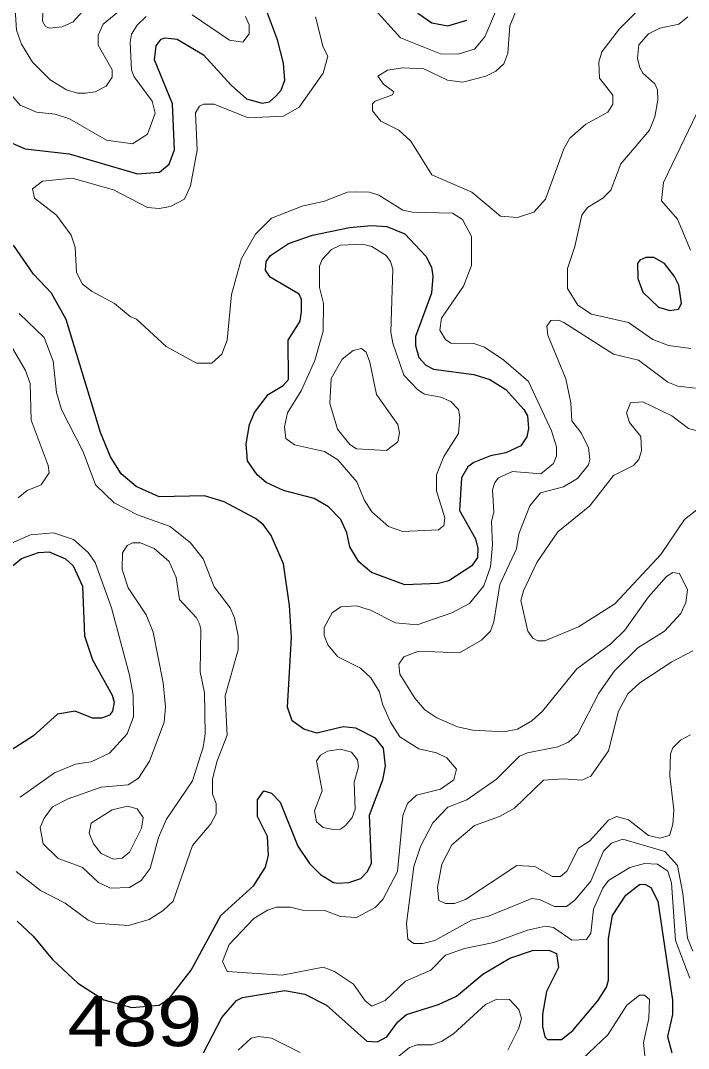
# Model space of a CAD drawing. Extents: x 577 to 602.9, y 7483.8 to 7511.6.
# Drawn here: x 583.474 to 584.536, y 7499.086 to 7500.722 of the extents above; entities that cross this region are included whole.
import ezdxf
from ezdxf.enums import TextEntityAlignment as Align

# ---------------------------------------------------------------- set-up
doc = ezdxf.new("R2010")
doc.units = 0
doc.header["$LTSCALE"] = 0.032
doc.layers.add('1', color=7, linetype='Continuous', lineweight=25)
doc.layers.add('2', color=7, linetype='Continuous', lineweight=13)
doc.layers.add('61', color=7, linetype='Continuous')

msp = doc.modelspace()

# ---------------------------------------------------------------- linework, layer by layer
at = {"layer": '1'}
for points in [[(583.3895, 7500.558), (583.4809, 7500.5182), (583.5509, 7500.5103), (583.6599, 7500.4785), (583.6948, 7500.4809), (583.71, 7500.4936), (583.7187, 7500.5166), (583.7155, 7500.5898), (583.6869, 7500.6598), (583.6893, 7500.682), (583.6972, 7500.6924), (583.7036, 7500.6948), (583.7227, 7500.6924), (583.7648, 7500.6677), (583.8086, 7500.6192), (583.8332, 7500.5977), (583.8579, 7500.5906), (583.8698, 7500.593), (583.8801, 7500.6017), (583.8881, 7500.6113), (583.8944, 7500.6272), (583.892, 7500.6542), (583.8825, 7500.6916), (583.8666, 7500.7337)], [(584.1059, 7500.7337), (584.1282, 7500.7186), (584.1537, 7500.7138), (584.1839, 7500.7226)], [(584.0384, 7499.5799), (584.0073, 7499.5958), (583.9867, 7499.5982), (583.9453, 7499.5879), (583.9246, 7499.5942), (583.9056, 7499.6078), (583.8984, 7499.6292), (583.9048, 7499.7405), (583.9016, 7499.7914), (583.892, 7499.8574), (583.8722, 7499.9028), (583.8602, 7499.9195), (583.8475, 7499.9298), (583.7974, 7499.956), (583.7664, 7499.9656), (583.694, 7499.964), (583.6575, 7499.9807), (583.6336, 7500.0006), (583.6169, 7500.0276), (583.601, 7500.0666), (583.5461, 7500.2463), (583.5231, 7500.2884), (583.4945, 7500.3186), (583.4627, 7500.3648)], [(583.4571, 7499.8511), (583.4754, 7499.8662), (583.5024, 7499.8757), (583.5191, 7499.8765), (583.5454, 7499.8654), (583.5573, 7499.8543), (583.5724, 7499.8217), (583.5756, 7499.7429), (583.5883, 7499.7048), (583.6193, 7499.6483), (583.6225, 7499.6372), (583.6201, 7499.6229), (583.6153, 7499.6165), (583.6026, 7499.6117), (583.5883, 7499.6117), (583.5605, 7499.6229), (583.5326, 7499.6181), (583.4945, 7499.5839), (583.4269, 7499.541)], [(583.4682, 7499.2889), (583.4937, 7499.265), (583.5247, 7499.2277), (583.5649, 7499.1902), (583.606, 7499.1637), (583.6506, 7499.1514), (583.694, 7499.1553), (583.71, 7499.1656), (583.7449, 7499.211), (583.7926, 7499.2976), (583.8451, 7499.3453), (583.8634, 7499.3748), (583.8682, 7499.3931), (583.8666, 7499.4233), (583.8507, 7499.4551), (583.8507, 7499.4821), (583.861, 7499.4964), (583.873, 7499.4925), (583.8865, 7499.4781), (583.9151, 7499.4082), (583.9334, 7499.3803), (583.9509, 7499.3628), (583.9716, 7499.3501), (583.9787, 7499.3493), (583.9962, 7499.3501), (584.0153, 7499.3565), (584.0256, 7499.3676), (584.032, 7499.3811), (584.0288, 7499.4575), (584.0503, 7499.5139), (584.0543, 7499.5354), (584.0511, 7499.564), (584.0384, 7499.5799)], [(583.7648, 7499.079), (583.7942, 7499.1354), (583.8173, 7499.1625), (583.8268, 7499.1672), (583.8944, 7499.1784), (583.9262, 7499.1728), (583.9604, 7499.1553), (584.0248, 7499.098), (584.0415, 7499.0965), (584.0566, 7499.1044), (584.0741, 7499.1283), (584.0877, 7499.1402), (584.1386, 7499.1561), (584.1672, 7499.1696), (584.2093, 7499.2046), (584.2523, 7499.23), (584.288, 7499.242), (584.3143, 7499.2428), (584.3262, 7499.2372), (584.3294, 7499.2149), (584.3103, 7499.1768), (584.3039, 7499.141), (584.3039, 7499.1211), (584.3079, 7499.1044), (584.3119, 7499.1004), (584.3342, 7499.1004), (584.3525, 7499.1147), (584.3922, 7499.1617), (584.4057, 7499.1839), (584.4089, 7499.1951), (584.4089, 7499.2611), (584.4153, 7499.2976), (584.4367, 7499.3302), (584.4582, 7499.3469), (584.467, 7499.3477), (584.4765, 7499.3422), (584.4876, 7499.3207), (584.5107, 7499.1632), (584.5107, 7499.1402), (584.5027, 7499.1052), (584.5099, 7499.079)]]:
    msp.add_lwpolyline(points, dxfattribs=at)
for points in [[(584.2205, 7500.1509), (584.2459, 7500.135), (584.2745, 7500.1031), (584.2801, 7500.0928), (584.2817, 7500.0729), (584.2793, 7500.0594), (584.2698, 7500.0451), (584.2459, 7500.034), (584.2212, 7500.0292), (584.195, 7500.0189), (584.1855, 7500.0117), (584.1751, 7499.9942), (584.1719, 7499.9425), (584.1974, 7499.8972), (584.2014, 7499.8821), (584.2006, 7499.8678), (584.1918, 7499.8543), (584.1552, 7499.8304), (584.1386, 7499.8264), (584.0853, 7499.824), (584.032, 7499.8439), (584.0121, 7499.8606), (583.9978, 7499.8845), (583.993, 7499.9067), (583.9835, 7499.9282), (583.9636, 7499.9481), (583.9406, 7499.9616), (583.892, 7499.9743), (583.8642, 7499.9871), (583.8499, 7499.999), (583.8348, 7500.0212), (583.8324, 7500.0483), (583.838, 7500.0793), (583.8459, 7500.0984), (583.8674, 7500.127), (583.8913, 7500.1413), (583.9, 7500.1509), (583.8992, 7500.2137), (583.9183, 7500.2439), (583.9207, 7500.259), (583.9207, 7500.2781), (583.9167, 7500.2868), (583.8706, 7500.3139), (583.8634, 7500.325), (583.8642, 7500.3385), (583.8714, 7500.3481), (583.9, 7500.3671), (583.9382, 7500.3807), (583.997, 7500.3926), (584.032, 7500.3958), (584.0566, 7500.3942), (584.0853, 7500.383), (584.1187, 7500.3473), (584.1274, 7500.3298), (584.1298, 7500.3155), (584.1274, 7500.2884), (584.102, 7500.2192), (584.102, 7500.2049), (584.1075, 7500.1858), (584.1187, 7500.1739), (584.1306, 7500.1676), (584.195, 7500.1588)], [(584.5141, 7500.315), (584.498, 7500.3353), (584.4813, 7500.3449), (584.4685, 7500.3449), (584.459, 7500.3409), (584.455, 7500.3353), (584.4558, 7500.3115), (584.4638, 7500.29), (584.4884, 7500.2662), (584.5067, 7500.2606), (584.5202, 7500.263), (584.525, 7500.2717), (584.521, 7500.3011)]]:
    msp.add_lwpolyline(points, close=True, dxfattribs=at)
at = {"layer": '2'}
for points in [[(583.6455, 7500.8252), (583.6543, 7500.8124), (583.6543, 7500.8021), (583.6471, 7500.7918), (583.605, 7500.7735), (583.5573, 7500.7202), (583.5398, 7500.7123), (583.5199, 7500.7099), (583.5135, 7500.713), (583.5088, 7500.721), (583.5096, 7500.7441), (583.5398, 7500.7751), (583.5644, 7500.8069), (583.578, 7500.8164), (583.6113, 7500.8276), (583.6304, 7500.8299)], [(584.1059, 7500.1342), (584.1163, 7500.1278), (584.1425, 7500.123), (584.1584, 7500.1159), (584.1704, 7500.1031), (584.1727, 7500.0912), (584.1704, 7500.065), (584.1473, 7500.0284), (584.1354, 7499.999), (584.1354, 7499.9735), (584.1489, 7499.9306), (584.1473, 7499.9187), (584.1386, 7499.9115), (584.0821, 7499.9091), (584.059, 7499.9171), (584.0328, 7499.9401), (584.0201, 7499.9592), (584.0089, 7499.9878), (583.9787, 7500.0228), (583.9573, 7500.0364), (583.9095, 7500.0467), (583.896, 7500.057), (583.8936, 7500.0753), (583.8984, 7500.0976), (583.9199, 7500.1326), (583.9421, 7500.1811), (583.9549, 7500.228), (583.9557, 7500.2717), (583.9493, 7500.2972), (583.9493, 7500.3314), (583.9533, 7500.3417), (583.9684, 7500.3576), (583.9827, 7500.3648), (584.0177, 7500.3663), (584.0328, 7500.3624), (584.0551, 7500.3481), (584.0622, 7500.3385), (584.0662, 7500.3266), (584.063, 7500.2264), (584.0662, 7500.2089), (584.0837, 7500.158)], [(584.0606, 7500.0976), (584.0741, 7500.0793), (584.0765, 7500.0658), (584.0741, 7500.0515), (584.0559, 7500.0379), (584.0081, 7500.0403), (583.9978, 7500.0475), (583.9779, 7500.0721), (583.966, 7500.1127), (583.9676, 7500.1524), (583.9851, 7500.1835), (584.0026, 7500.197), (584.0161, 7500.2002), (584.0233, 7500.1946), (584.0296, 7500.1787), (584.0399, 7500.127)], [(583.5628, 7499.3779), (583.5724, 7499.374), (583.5978, 7499.3501), (583.6169, 7499.3414), (583.6471, 7499.3422), (583.6654, 7499.3533), (583.6797, 7499.3724), (583.6933, 7499.4217), (583.706, 7499.4511), (583.7473, 7499.5123), (583.764, 7499.5656), (583.7672, 7499.5871), (583.7664, 7499.6523), (583.7593, 7499.6857), (583.7608, 7499.7533), (583.7585, 7499.762), (583.7537, 7499.7716), (583.7267, 7499.801), (583.7211, 7499.836), (583.71, 7499.8614), (583.6861, 7499.8821), (583.6646, 7499.8908), (583.6519, 7499.8908), (583.6432, 7499.8869), (583.636, 7499.8749), (583.6352, 7499.8487), (583.6447, 7499.8193), (583.6734, 7499.7763), (583.6845, 7499.7485), (583.7004, 7499.6682), (583.7044, 7499.63), (583.702, 7499.6054), (583.6789, 7499.5433), (583.6614, 7499.5163), (583.6447, 7499.506), (583.6018, 7499.502), (583.5493, 7499.4837), (583.5247, 7499.471), (583.5112, 7499.4527), (583.5048, 7499.4376), (583.5096, 7499.4121), (583.5334, 7499.3883)], [(583.9716, 7499.4344), (583.9827, 7499.4352), (583.9906, 7499.4408), (584.001, 7499.4535), (584.0058, 7499.467), (584.0042, 7499.5099), (584.0113, 7499.5346), (584.0097, 7499.5457), (584.0002, 7499.5577), (583.9827, 7499.5624), (583.962, 7499.5592), (583.9509, 7499.5529), (583.9445, 7499.5441), (583.9533, 7499.4964), (583.9413, 7499.4646), (583.9445, 7499.4471), (583.9549, 7499.4376)], [(583.5899, 7499.4121), (583.6018, 7499.3962), (583.6217, 7499.3875), (583.6352, 7499.3891), (583.6471, 7499.3986), (583.6662, 7499.4368), (583.6686, 7499.4535), (583.6591, 7499.4678), (583.644, 7499.4718), (583.6193, 7499.4662), (583.5859, 7499.4447), (583.5827, 7499.4288)]]:
    msp.add_lwpolyline(points, close=True, dxfattribs=at)
for points in [[(584.4805, 7500.7639), (584.4264, 7500.7091), (584.3986, 7500.6725), (584.3938, 7500.6558), (584.3946, 7500.6303), (584.4161, 7500.6033), (584.4161, 7500.589), (584.4081, 7500.5763), (584.3731, 7500.5572), (584.3477, 7500.5349), (584.3381, 7500.5182), (584.3087, 7500.4379), (584.2904, 7500.4172), (584.2642, 7500.4085), (584.2372, 7500.4109), (584.1918, 7500.449), (584.1282, 7500.4769), (584.0948, 7500.5302), (584.0757, 7500.5476), (584.0471, 7500.562), (584.0336, 7500.5787), (584.0336, 7500.5898), (584.0376, 7500.5938), (584.0654, 7500.6041), (584.0678, 7500.6089), (584.0511, 7500.6208), (584.0423, 7500.6335), (584.0574, 7500.6431), (584.0821, 7500.647), (584.1155, 7500.6455), (584.1529, 7500.6272), (584.1775, 7500.624), (584.2141, 7500.6335), (584.23, 7500.6415), (584.2427, 7500.6534), (584.2491, 7500.6701), (584.2523, 7500.7138), (584.261, 7500.7353)], [(583.3664, 7500.748), (583.3728, 7500.7083), (583.3967, 7500.6733), (583.4515, 7500.6248), (583.4603, 7500.6025), (583.473, 7500.5874), (583.4992, 7500.5763), (583.5287, 7500.5731), (583.5517, 7500.5659), (583.6106, 7500.5317), (583.6519, 7500.5262), (583.6758, 7500.5413), (583.6877, 7500.5747), (583.6829, 7500.5938), (583.6543, 7500.6327), (583.6503, 7500.6431), (583.6479, 7500.6876), (583.6503, 7500.7003), (583.6591, 7500.7146), (583.6734, 7500.7289)], [(583.6344, 7500.7401), (583.605, 7500.7162), (583.597, 7500.6987), (583.597, 7500.6828), (583.6193, 7500.6439), (583.6193, 7500.6319), (583.6098, 7500.6176), (583.5923, 7500.6089), (583.5772, 7500.6065), (583.5644, 7500.6065), (583.5469, 7500.6121), (583.5207, 7500.628), (583.4929, 7500.6558), (583.4754, 7500.6844), (583.4674, 7500.7067), (583.465, 7500.7401)], [(584.2324, 7500.7433), (584.2125, 7500.6963), (584.1958, 7500.6765), (584.1696, 7500.6685), (584.1417, 7500.6693), (584.0781, 7500.6948), (584.0376, 7500.7393)], [(583.9429, 7500.7282), (583.9549, 7500.6796), (583.9628, 7500.6653), (583.9549, 7500.6383), (583.9167, 7500.5842), (583.892, 7500.5699), (583.8356, 7500.5675), (583.7815, 7500.589), (583.7648, 7500.589), (583.7585, 7500.5858), (583.7521, 7500.5755), (583.7545, 7500.5158), (583.7441, 7500.4594), (583.7346, 7500.4379), (583.7123, 7500.426), (583.694, 7500.4228), (583.6758, 7500.4244)], [(583.7465, 7500.7313), (583.8062, 7500.6908), (583.8276, 7500.6876), (583.8372, 7500.7011), (583.8372, 7500.7154), (583.8316, 7500.7289)], [(584.5401, 7500.2002), (584.5043, 7500.2049), (584.4797, 7500.2145), (584.4407, 7500.2415), (584.3819, 7500.255), (584.3604, 7500.2693), (584.3437, 7500.2956), (584.3437, 7500.3274), (584.3556, 7500.3624), (584.3668, 7500.4125), (584.3755, 7500.4244), (584.4002, 7500.4395), (584.4129, 7500.4522), (584.4288, 7500.4944), (584.4741, 7500.5476), (584.4829, 7500.5691), (584.4876, 7500.5954), (584.4868, 7500.6121), (584.4829, 7500.6216), (584.4638, 7500.6383), (584.459, 7500.647), (584.455, 7500.6622), (584.4574, 7500.6836), (584.4725, 7500.7011), (584.4908, 7500.7099), (584.521, 7500.7162), (584.5353, 7500.7282)], [(584.5497, 7500.5747), (584.4964, 7500.4642), (584.4932, 7500.4355), (584.5186, 7500.4061), (584.5393, 7500.3568)], [(583.6758, 7500.4244), (583.6217, 7500.453), (583.5557, 7500.4713), (583.5088, 7500.4665), (583.4929, 7500.4546), (583.496, 7500.4395), (583.531, 7500.4125), (583.5541, 7500.3807), (583.5605, 7500.3616), (583.5628, 7500.321), (583.5724, 7500.3027), (583.5875, 7500.2908), (583.6233, 7500.2717), (583.6479, 7500.251), (583.6583, 7500.2471), (583.7052, 7500.2033), (583.7537, 7500.1771), (583.7783, 7500.1771), (583.7942, 7500.1914), (583.8022, 7500.2137), (583.8093, 7500.286), (583.8253, 7500.3433), (583.8475, 7500.3823), (583.873, 7500.4077), (583.9215, 7500.4268), (583.9573, 7500.4347), (583.9938, 7500.449), (584.0089, 7500.4498), (584.0288, 7500.449), (584.0439, 7500.4443), (584.0821, 7500.4204), (584.0972, 7500.4172), (584.1608, 7500.4157), (584.1767, 7500.4053), (584.191, 7500.3783), (584.191, 7500.3322), (584.1783, 7500.2996), (584.1433, 7500.2487), (584.1409, 7500.2296), (584.1497, 7500.2145), (584.1584, 7500.2089), (584.195, 7500.2081), (584.2117, 7500.2025), (584.2427, 7500.1819), (584.2817, 7500.1477), (584.3183, 7500.069), (584.3262, 7500.0435), (584.3262, 7500.0292), (584.3214, 7500.0173), (584.3016, 7500.0006), (584.2562, 7500.0045), (584.234, 7499.9942), (584.2284, 7499.9871), (584.2244, 7499.9751), (584.2268, 7499.9401), (584.2228, 7499.925), (584.2244, 7499.8877), (584.2212, 7499.8527), (584.2109, 7499.8224), (584.1879, 7499.7946), (584.16, 7499.7795), (584.1044, 7499.7604), (584.0702, 7499.7636), (584.0304, 7499.7835), (584.0081, 7499.7906), (583.9835, 7499.7891), (583.9692, 7499.7795), (583.9565, 7499.7564), (583.9565, 7499.7437), (583.9628, 7499.7286), (583.9787, 7499.7095), (584.0145, 7499.6912), (584.0312, 7499.6761), (584.0447, 7499.6539), (584.0495, 7499.634), (584.0622, 7499.6054), (584.0773, 7499.5823), (584.1075, 7499.5632), (584.1354, 7499.5569), (584.1521, 7499.5489), (584.1672, 7499.5306), (584.1632, 7499.5139), (584.1417, 7499.4988), (584.1036, 7499.4893), (584.0893, 7499.4758), (584.0821, 7499.4567), (584.0733, 7499.3676), (584.0503, 7499.3231), (584.0376, 7499.3104), (584.0081, 7499.2945), (583.9827, 7499.296), (583.958, 7499.3056), (583.9223, 7499.3064), (583.9032, 7499.3112), (583.8809, 7499.3112), (583.8666, 7499.3064), (583.8451, 7499.2929), (583.8054, 7499.2515), (583.795, 7499.2245), (583.8022, 7499.2086), (583.8897, 7499.203)], [(583.4714, 7500.2558), (583.5112, 7500.2177), (583.5255, 7500.1803), (583.531, 7500.1302), (583.539, 7500.1031), (583.5732, 7500.0356), (583.5931, 7499.9831), (583.6225, 7499.9544), (583.6599, 7499.9354), (583.7115, 7499.9171), (583.7441, 7499.8908), (583.764, 7499.8654), (583.7815, 7499.8209), (583.807, 7499.7875), (583.8141, 7499.7716), (583.8197, 7499.7429), (583.8197, 7499.7207), (583.799, 7499.6475), (583.8022, 7499.5847), (583.7863, 7499.5441), (583.7791, 7499.5155), (583.7791, 7499.4909), (583.7847, 7499.4758), (583.7847, 7499.4598), (583.7767, 7499.4439), (583.7473, 7499.409), (583.7163, 7499.3207), (583.7004, 7499.3056), (583.6781, 7499.2913), (583.6455, 7499.2817), (583.5931, 7499.2857), (583.5811, 7499.2905), (583.5446, 7499.3175), (583.5056, 7499.3374), (583.4666, 7499.3676)], [(584.5433, 7499.2412), (584.5345, 7499.2618), (584.5274, 7499.3326), (584.5186, 7499.3772), (584.4988, 7499.3994), (584.432, 7499.4193), (584.4137, 7499.4129), (584.401, 7499.4002), (584.3811, 7499.3525), (584.3556, 7499.3223), (584.3421, 7499.3119), (584.323, 7499.3119), (584.2992, 7499.3231), (584.2872, 7499.3247), (584.2181, 7499.2968), (584.191, 7499.2905), (584.133, 7499.2579), (584.1139, 7499.2531), (584.0996, 7499.2531), (584.09, 7499.2603), (584.0877, 7499.2849), (584.0996, 7499.3756), (584.1099, 7499.4074), (584.1298, 7499.4455), (584.1537, 7499.4702), (584.1839, 7499.4821), (584.2308, 7499.5147), (584.2674, 7499.5513), (584.2801, 7499.5569), (584.3286, 7499.5664), (584.3453, 7499.5736), (584.3604, 7499.5871), (584.3938, 7499.6515), (584.4185, 7499.6873), (584.4558, 7499.7238), (584.498, 7499.7501), (584.5242, 7499.7787), (584.5322, 7499.7962), (584.5345, 7499.8161), (584.5218, 7499.8423), (584.5115, 7499.8439), (584.5012, 7499.8376), (584.4725, 7499.805), (584.4352, 7499.7517), (584.4129, 7499.7302), (584.3588, 7499.6904), (584.3039, 7499.6229), (584.2872, 7499.6078), (584.2642, 7499.5942), (584.2427, 7499.5903), (584.1934, 7499.5926), (584.1688, 7499.5982), (584.1362, 7499.6125), (584.1171, 7499.6252), (584.1012, 7499.6435), (584.0773, 7499.6817), (584.0757, 7499.6976), (584.0837, 7499.7095), (584.1067, 7499.7183), (584.1719, 7499.7159), (584.2069, 7499.7358), (584.2212, 7499.7501), (584.2268, 7499.7652), (584.2364, 7499.8248), (584.2626, 7499.8813), (584.2666, 7499.9051), (584.2841, 7499.9497), (584.3008, 7499.9704), (584.3373, 7499.9799), (584.3596, 7499.9934), (584.3771, 7500.0149), (584.3795, 7500.0236), (584.3771, 7500.0427), (584.3652, 7500.0666), (584.3509, 7500.0849), (584.3493, 7500.1135), (584.3413, 7500.1517), (584.3127, 7500.2216), (584.3111, 7500.2359), (584.3175, 7500.2447), (584.3294, 7500.2455), (584.3381, 7500.2415), (584.4169, 7500.1914), (584.4566, 7500.1819), (584.5035, 7500.1469), (584.5194, 7500.1405), (584.5473, 7500.1373)], [(583.446, 7500.2264), (583.4817, 7500.1652), (583.4889, 7500.1445), (583.4905, 7500.0864), (583.5175, 7500.0141), (583.5191, 7500.0022), (583.5064, 7499.9831), (583.4841, 7499.9743), (583.4698, 7499.9624)], [(584.556, 7500.0674), (584.5361, 7500.0729), (584.5099, 7500.0928), (584.4638, 7500.1151), (584.4439, 7500.1135), (584.4375, 7500.0976), (584.4423, 7500.0825), (584.4606, 7500.0602), (584.4614, 7500.0371), (584.4574, 7500.0236), (584.4487, 7500.0141), (584.4169, 7499.9982), (584.3795, 7499.9497), (584.3286, 7499.9083), (584.2952, 7499.8598), (584.2737, 7499.8145), (584.2698, 7499.7994), (584.2809, 7499.7501), (584.2888, 7499.739), (584.2968, 7499.735), (584.3079, 7499.735), (584.3612, 7499.7572), (584.4192, 7499.7938), (584.4924, 7499.8725), (584.5298, 7499.9282), (584.552, 7499.9457)], [(583.473, 7499.4861), (583.5279, 7499.5251), (583.5613, 7499.5386), (583.5859, 7499.5425), (583.6153, 7499.5561), (583.6432, 7499.5871), (583.6535, 7499.6141), (583.6527, 7499.6483), (583.6471, 7499.6801), (583.6185, 7499.7875), (583.5923, 7499.8598), (583.5811, 7499.8757), (583.5581, 7499.8964), (583.5263, 7499.9067), (583.4897, 7499.9036), (583.4547, 7499.8884)], [(584.5433, 7499.7191), (584.5099, 7499.7016), (584.459, 7499.6682), (584.4399, 7499.6507), (584.4248, 7499.6229), (584.4089, 7499.56), (584.3811, 7499.5195), (584.3668, 7499.5131), (584.3373, 7499.5155), (584.3055, 7499.5131), (584.2594, 7499.4686), (584.2356, 7499.4551), (584.1958, 7499.4408), (584.16, 7499.4105), (584.1441, 7499.3795), (584.137, 7499.3422), (584.1393, 7499.3215), (584.1497, 7499.3167), (584.164, 7499.3167), (584.1815, 7499.3231), (584.2634, 7499.3772), (584.292, 7499.3756), (584.3199, 7499.3597), (584.3326, 7499.3597), (584.3429, 7499.3684), (584.3612, 7499.405), (584.3787, 7499.4161), (584.4089, 7499.4495), (584.4216, 7499.4551), (584.4407, 7499.4503), (584.4725, 7499.4249), (584.4908, 7499.4209), (584.5059, 7499.4249), (584.5115, 7499.4424), (584.5131, 7499.4662), (584.5067, 7499.5203), (584.5075, 7499.5553), (584.5115, 7499.5648), (584.5234, 7499.5767), (584.5393, 7499.5855)], [(583.8897, 7499.203), (583.9549, 7499.2157), (583.9732, 7499.2086), (584.0034, 7499.1887), (584.0217, 7499.1617), (584.0328, 7499.1537), (584.0535, 7499.1625), (584.0861, 7499.1935), (584.1266, 7499.211), (584.1497, 7499.2348), (584.1799, 7499.2452), (584.2268, 7499.2547), (584.2801, 7499.2746), (584.3087, 7499.2809), (584.3214, 7499.2785), (584.3509, 7499.2587), (584.3739, 7499.2595), (584.3811, 7499.2698), (584.3851, 7499.308), (584.4002, 7499.3414), (584.4089, 7499.3533), (584.4431, 7499.374), (584.4662, 7499.3803), (584.4868, 7499.3795), (584.5035, 7499.3684), (584.5092, 7499.3496), (584.5155, 7499.2579), (584.5385, 7499.1982)], [(584.0702, 7499.0694), (584.0924, 7499.0877), (584.1044, 7499.0917), (584.1282, 7499.0917), (584.1433, 7499.0972), (584.1624, 7499.1092), (584.2133, 7499.1561), (584.2316, 7499.1648), (584.2515, 7499.164), (584.2666, 7499.1481), (584.2706, 7499.1338), (584.2666, 7499.1187), (584.2491, 7499.0837)], [(584.3676, 7499.0694), (584.4081, 7499.1076), (584.4383, 7499.1553), (584.4582, 7499.1712), (584.4662, 7499.1712), (584.4741, 7499.164), (584.4733, 7499.1338), (584.4646, 7499.0957), (584.4678, 7499.0646)], [(583.8197, 7499.0837), (583.8404, 7499.1028), (583.8523, 7499.1052), (583.873, 7499.1028), (583.9183, 7499.0798)]]:
    msp.add_lwpolyline(points, dxfattribs=at)

# ---------------------------------------------------------------- texts
at = {"layer": '61', "width": 1.2}
msp.add_text('489', height=0.08, dxfattribs=at).set_placement((583.6554, 7499.0898), align=Align.CENTER)

doc.saveas('drawing.dxf')
